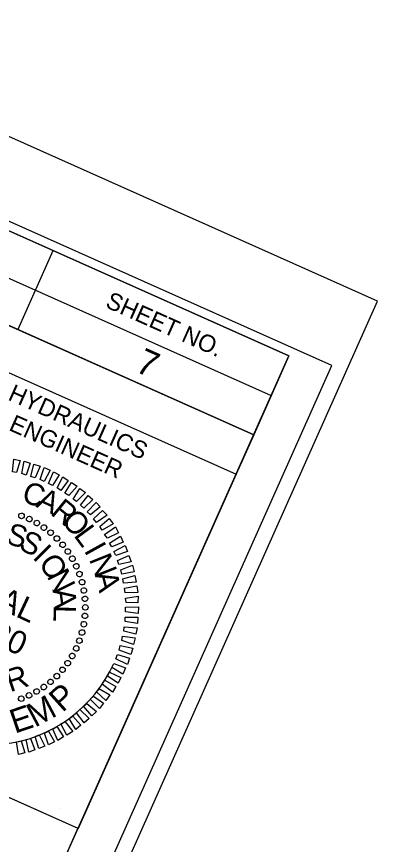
# Model space of a CAD drawing. Extents: x 2297991 to 2299183, y 599186 to 600200.
# Drawn here: x 2299120 to 2299182.8, y 599694 to 599838.1 of the extents above; entities that cross this region are included whole.
import ezdxf

# ---------------------------------------------------------------- set-up
doc = ezdxf.new("R2010")
doc.units = 0
for name, color, linetype in [('Exist DTM Drainline Cogo Elevation', 7, 'Continuous'), ('Exist DTM Drainline Cogo Number', 7, 'Continuous'), ('Exist DTM Drainline Cogo Point CELL', 7, 'Continuous'), ('Exist Roads Curbs Cogo Elevation', 7, 'Continuous'), ('Exist Roads EOP Cogo Comment', 7, 'Continuous'), ('Exist Roads EOP Cogo Point CELL', 7, 'Continuous'), ('Exist Roads EOP Other Cogo Number', 7, 'Continuous')]:
    doc.layers.add(name, color=color, linetype=linetype)

msp = doc.modelspace()

# ---------------------------------------------------------------- linework, layer by layer
at = {"layer": 'Exist DTM Drainline Cogo Elevation'}
msp.add_lwpolyline([(2299182.82, 599788.6), (2298260.17, 600200.46), (2297991.14, 599597.77), (2298913.79, 599185.92)], close=True, dxfattribs=at)
at = {"layer": 'Exist DTM Drainline Cogo Number'}
msp.add_lwpolyline([(2299174.87, 599777.4), (2298261.8, 600184.98), (2298003.76, 599606.9), (2298916.82, 599199.32)], close=True, dxfattribs=at)
at = {"layer": 'Exist DTM Drainline Cogo Point CELL'}
for p, q in [((2299054.72, 599821.11), (2299164.32, 599772.18)), ((2299051.66, 599814.26), (2299161.27, 599765.33)), ((2299051.66, 599814.26), (2299161.27, 599765.33)), ((2299126.29, 599797.37), (2299120.17, 599783.68)), ((2299161.27, 599765.33), (2299158.21, 599758.49))]:
    msp.add_line(p, q, dxfattribs=at)
for points in [[(2299167.39, 599779.06), (2298345.56, 600145.92), (2298088.76, 599570.63), (2298910.59, 599203.77)], [(2299057.79, 599827.99), (2299167.39, 599779.06), (2299161.27, 599765.33), (2299051.66, 599814.26)], [(2299103.42, 599782.94), (2299158.21, 599758.49), (2299130.7, 599696.85), (2299075.91, 599721.31)]]:
    msp.add_lwpolyline(points, close=True, dxfattribs=at)
at = {"layer": 'Exist Roads Curbs Cogo Elevation'}
msp.add_lwpolyline([(2299021.09, 599745.77), (2299130.67, 599696.86), (2299124.25, 599682.48), (2299014.67, 599731.39)], close=True, dxfattribs=at)
at = {"layer": 'Exist Roads EOP Cogo Comment'}
msp.add_arc((2299115.02, 599735.33), 23.96, 155.9448, 335.9448, dxfattribs=at)
at = {"layer": 'Exist Roads EOP Other Cogo Number'}
for p, q in [((2299120.83, 599751.25), (2299120.83, 599751.25)), ((2299122.2, 599750.68), (2299122.2, 599750.68)), ((2299123.52, 599749.98), (2299123.52, 599749.98)), ((2299124.75, 599749.17), (2299124.75, 599749.17)), ((2299125.92, 599748.32), (2299125.92, 599748.32)), ((2299127.02, 599747.31), (2299127.02, 599747.31)), ((2299128, 599746.2), (2299128, 599746.2)), ((2299128.93, 599745.05), (2299128.93, 599745.05)), ((2299129.7, 599743.78), (2299129.7, 599743.78)), ((2299130.4, 599742.47), (2299130.4, 599742.47)), ((2299130.95, 599741.12), (2299130.95, 599741.12)), ((2299131.42, 599739.69), (2299131.42, 599739.69)), ((2299131.71, 599738.27), (2299131.71, 599738.27)), ((2299131.89, 599736.78), (2299131.89, 599736.78)), ((2299131.97, 599735.3), (2299131.97, 599735.3)), ((2299131.92, 599733.85), (2299131.92, 599733.85)), ((2299131.71, 599732.39), (2299131.71, 599732.39)), ((2299131.35, 599730.92), (2299131.35, 599730.92)), ((2299130.94, 599729.52), (2299130.94, 599729.52)), ((2299130.37, 599728.15), (2299130.37, 599728.15)), ((2299129.67, 599726.83), (2299129.67, 599726.83)), ((2299128.86, 599725.6), (2299128.86, 599725.6)), ((2299128.01, 599724.43), (2299128.01, 599724.43)), ((2299125.89, 599722.35), (2299125.89, 599722.35)), ((2299127, 599723.33), (2299127, 599723.33)), ((2299123.47, 599720.65), (2299123.47, 599720.65)), ((2299124.74, 599721.42), (2299124.74, 599721.42)), ((2299120.81, 599719.4), (2299120.81, 599719.4)), ((2299122.16, 599719.95), (2299122.16, 599719.95)), ((2299127.58, 599700.38), (2299127.58, 599700.38))]:
    msp.add_line(p, q, dxfattribs=at)
for points in [[(2299119.26, 599758.9), (2299119.48, 599761.13), (2299120.62, 599760.88), (2299119.98, 599758.77)], [(2299120.89, 599758.58), (2299121.28, 599760.77), (2299122.34, 599760.41), (2299121.67, 599758.34)], [(2299122.45, 599758.11), (2299122.99, 599760.23), (2299124.1, 599759.89), (2299123.23, 599757.87)], [(2299124.06, 599757.57), (2299124.8, 599759.64), (2299125.8, 599759.16), (2299124.79, 599757.21)], [(2299125.53, 599756.88), (2299126.42, 599758.88), (2299127.42, 599758.4), (2299126.25, 599756.52)], [(2299127.03, 599756.1), (2299128.04, 599758.05), (2299128.98, 599757.41), (2299127.71, 599755.65)], [(2299128.4, 599755.19), (2299129.55, 599757.04), (2299130.5, 599756.43), (2299129.09, 599754.77)], [(2299129.82, 599754.15), (2299131.02, 599756.02), (2299131.96, 599755.3), (2299130.39, 599753.71)], [(2299131.12, 599753.09), (2299132.43, 599754.8), (2299133.25, 599754.06), (2299131.67, 599752.59)], [(2299132.26, 599751.92), (2299133.83, 599753.54), (2299134.53, 599752.79), (2299132.87, 599751.39)], [(2299133.38, 599750.71), (2299134.96, 599752.19), (2299135.73, 599751.33), (2299133.91, 599750.07)], [(2299134.48, 599749.37), (2299136.1, 599750.76), (2299136.79, 599749.82), (2299134.9, 599748.74)], [(2299135.31, 599748), (2299137.19, 599749.31), (2299137.7, 599748.3), (2299135.83, 599747.33)], [(2299136.16, 599746.51), (2299138.06, 599747.7), (2299138.56, 599746.67), (2299136.56, 599745.82)], [(2299136.91, 599745.04), (2299138.89, 599746.08), (2299139.3, 599745.01), (2299137.29, 599744.31)], [(2299137.54, 599743.46), (2299139.51, 599744.32), (2299139.92, 599743.25), (2299137.78, 599742.76)], [(2299138.12, 599741.87), (2299140.16, 599742.63), (2299140.43, 599741.5), (2299138.28, 599741.06)], [(2299138.51, 599740.26), (2299140.6, 599740.88), (2299140.78, 599739.72), (2299138.62, 599739.51)], [(2299138.75, 599738.64), (2299140.9, 599739.08), (2299141.07, 599737.89), (2299138.9, 599737.83)], [(2299138.94, 599736.92), (2299141.15, 599737.23), (2299141.12, 599736.1), (2299139.05, 599736.17)], [(2299138.97, 599735.32), (2299141.2, 599735.43), (2299141.16, 599734.27), (2299138.97, 599734.51)], [(2299138.87, 599733.63), (2299141.11, 599733.59), (2299141.02, 599732.48), (2299138.89, 599732.84)], [(2299138.71, 599731.93), (2299141, 599731.75), (2299140.73, 599730.66), (2299138.63, 599731.18)], [(2299138.42, 599730.28), (2299140.62, 599730), (2299140.34, 599728.87), (2299138.31, 599729.55)], [(2299138.03, 599728.68), (2299140.23, 599728.22), (2299139.85, 599727.13), (2299137.83, 599727.88)], [(2299137.56, 599727.12), (2299139.67, 599726.47), (2299139.27, 599725.39), (2299137.29, 599726.35)], [(2299136.9, 599725.56), (2299138.95, 599724.76), (2299138.48, 599723.71), (2299136.57, 599724.82)], [(2299136.18, 599724.04), (2299138.16, 599723.08), (2299137.64, 599722.09), (2299135.79, 599723.32)], [(2299135.37, 599722.62), (2299137.26, 599721.56), (2299136.67, 599720.57), (2299134.88, 599721.95)], [(2299134.42, 599721.16), (2299136.22, 599720.06), (2299135.54, 599719.11), (2299133.88, 599720.63)], [(2299133.36, 599719.86), (2299135.09, 599718.61), (2299134.42, 599717.69), (2299132.82, 599719.33)], [(2299132.24, 599718.59), (2299133.9, 599717.18), (2299133.07, 599716.41), (2299131.61, 599718.09)], [(2299129.77, 599716.37), (2299131.18, 599714.81), (2299130.29, 599714.06), (2299129.13, 599715.95)], [(2299131.01, 599717.51), (2299132.61, 599715.95), (2299131.72, 599715.2), (2299130.4, 599716.97)], [(2299128.43, 599715.37), (2299129.75, 599713.68), (2299128.75, 599713.09), (2299127.69, 599715.04)], [(2299125.51, 599713.79), (2299126.58, 599711.88), (2299125.54, 599711.38), (2299124.83, 599713.43)], [(2299126.96, 599714.55), (2299128.16, 599712.76), (2299127.17, 599712.13), (2299126.3, 599714.14)], [(2299120.75, 599712.07), (2299121.42, 599710), (2299120.3, 599709.73), (2299119.99, 599711.93)], [(2299122.41, 599712.48), (2299123.16, 599710.52), (2299122.09, 599710.11), (2299121.63, 599712.31)], [(2299123.91, 599713.1), (2299124.92, 599711.14), (2299123.83, 599710.77), (2299123.2, 599712.83)]]:
    msp.add_lwpolyline(points, close=True, dxfattribs=at)
for centre, major_axis in [((2299120.83, 599751.23), (0.167, 0.457)), ((2299122.19, 599750.67), (0.206, 0.44)), ((2299123.5, 599749.98), (0.243, 0.421)), ((2299124.74, 599749.19), (0.279, 0.398)), ((2299125.91, 599748.29), (0.313, 0.372)), ((2299127, 599747.29), (0.344, 0.343)), ((2299128, 599746.2), (0.373, 0.312)), ((2299128.9, 599745.03), (0.398, 0.278)), ((2299129.69, 599743.78), (0.421, 0.243)), ((2299130.37, 599742.47), (0.441, 0.205)), ((2299130.93, 599741.1), (0.457, 0.166)), ((2299131.38, 599739.7), (0.47, 0.125)), ((2299131.69, 599738.25), (0.479, 0.084)), ((2299131.89, 599736.79), (0.484, 0.042)), ((2299131.95, 599735.31), (0.486, 0)), ((2299131.88, 599733.84), (0.484, -0.043)), ((2299131.69, 599732.37), (0.479, -0.085)), ((2299131.37, 599730.93), (0.469, -0.126)), ((2299130.92, 599729.52), (0.457, -0.167)), ((2299130.36, 599728.16), (0.44, -0.206)), ((2299129.67, 599726.85), (0.421, -0.243)), ((2299127.98, 599724.44), (0.372, -0.313)), ((2299128.88, 599725.61), (0.398, -0.279)), ((2299126.98, 599723.35), (0.343, -0.344)), ((2299124.72, 599721.45), (0.278, -0.398)), ((2299125.89, 599722.35), (0.312, -0.373)), ((2299122.16, 599719.98), (0.205, -0.441)), ((2299123.47, 599720.66), (0.243, -0.421)), ((2299120.79, 599719.42), (0.166, -0.457))]:
    msp.add_ellipse(centre, major_axis=major_axis, ratio=0.999708, dxfattribs=at)

# ---------------------------------------------------------------- texts
at = {"layer": 'Exist DTM Drainline Cogo Point CELL'}
for s, p in [('SHEET NO.', (2299135.27, 599787.62)), ('HYDRAULICS', (2299118.32, 599771.5)), ('ENGINEER', (2299118.46, 599766.21))]:
    msp.add_text(s, height=3, rotation=335.9448, dxfattribs=at).set_placement(p)
at = {"layer": 'Exist Roads EOP Cogo Point CELL'}
msp.add_text('7', height=4.5, rotation=335.9448, dxfattribs=at).set_placement((2299140.44, 599776.47))
at = {"layer": 'Exist Roads EOP Other Cogo Number'}
for s, height, rotation, p in [('C', 3.81, 342.1646, (2299120.69, 599753.75)), ('A', 3.81, 334.9651, (2299123.21, 599752.85)), ('R', 3.83, 320.5659, (2299125.74, 599751.57)), ('O', 3.86, 313.3659, (2299127.6, 599750.19)), ('S', 3.81, 343.2004, (2299117.93, 599746.49)), ('L', 3.89, 306.1656, (2299129.81, 599747.84)), ('S', 3.81, 333.8452, (2299120.16, 599745.53)), ('I', 3.92, 298.9649, (2299131.64, 599745.24)), ('I', 3.86, 315.1344, (2299122.62, 599743.91)), ('O', 3.89, 305.7782, (2299123.66, 599742.93)), ('N', 3.93, 291.7637, (2299132.54, 599743.7)), ('N', 3.92, 296.4214, (2299125.18, 599740.78)), ('SEAL', 4.049, 334.9448, (2299109.84, 599738.38)), ('A', 3.93, 284.5619, (2299133.55, 599741.07)), ('047680', 4.05, 334.9448, (2299104.22, 599734.45)), ('A', 3.92, 277.705, (2299126.22, 599738.39)), ('L', 3.88, 268.3456, (2299126.47, 599735.73)), ('R', 3.93, 18.4262, (2299118.83, 599720.51)), ('P', 4.13, 41.927, (2299127.95, 599716.91)), ('M', 4.18, 28.112, (2299123.17, 599714.35)), ('E', 4.18, 18.7974, (2299119.67, 599713.31))]:
    msp.add_text(s, height=height, rotation=rotation, dxfattribs=at).set_placement(p)

doc.saveas('drawing.dxf')
